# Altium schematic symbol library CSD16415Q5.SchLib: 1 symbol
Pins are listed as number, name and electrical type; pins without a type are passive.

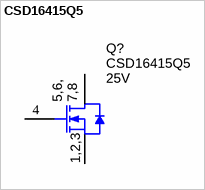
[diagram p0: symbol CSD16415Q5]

## CSD16415Q5
designator Q?  value 25V
MOSFET N-CH 25V 8SON; Manufacturer: Texas Instruments; U/M: EA; ChType: N; VdsMax_V: 25; Value1: 0.0015 ohm; Rdson45_Ohm: 0.0033; Value2: 21 nC; QgTyp_nC: 19; Vgs_V: 12; IdsMax_A: 100
simulation model csd17501q5a
footprint Q5A (TI recommended land pattern (nominal) M0139-01)
footprint Q5A WITH VIAS (TI 15A WITH VIAS)
pins: 1 S, 2 S, 3 S, 4 G, 5 D, 6 D, 7 D, 8 D, 9 D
